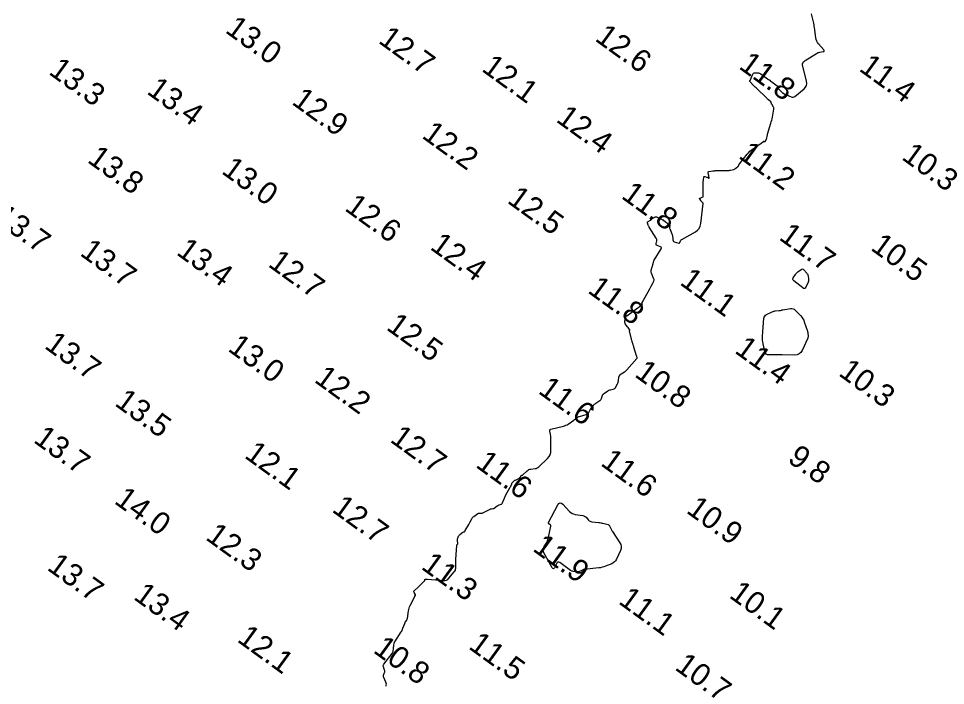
# Model space of a CAD drawing. Extents: x 815352 to 820877, y 582403 to 597439.
# Drawn here: x 818763.1 to 818971.4, y 587063.7 to 587213.7 of the extents above; entities that cross this region are included whole.
import ezdxf

# ---------------------------------------------------------------- set-up
doc = ezdxf.new("R2010")
doc.units = 0
doc.layers.add('V-CONT-EL12', color=7, linetype='Continuous')
doc.layers.add('V-TOPO-SOUN', color=7, linetype='Continuous')

msp = doc.modelspace()

# ---------------------------------------------------------------- linework, layer by layer
at = {"layer": 'V-CONT-EL12'}
msp.add_lwpolyline([(818845.72, 587063.57), (818845.78, 587063.79), (818845.8, 587064), (818845.77, 587064.21), (818845.7, 587064.41), (818845.21, 587065.49), (818845.17, 587065.62), (818845.15, 587065.76), (818845.16, 587065.9), (818845.19, 587066.03), (818845.38, 587066.59), (818845.42, 587066.73), (818845.43, 587066.87), (818845.42, 587067.01), (818845.38, 587067.15), (818845.14, 587067.86), (818845.1, 587068.02), (818845.11, 587068.17), (818845.15, 587068.32), (818845.24, 587068.46), (818847.11, 587070.91), (818847.18, 587071.02), (818847.24, 587071.13), (818847.28, 587071.25), (818847.3, 587071.38), (818847.4, 587072.05), (818847.4, 587072.11), (818847.41, 587072.17), (818847.42, 587072.23), (818847.43, 587072.28), (818847.45, 587072.51), (818847.46, 587072.57), (818847.47, 587072.63), (818847.48, 587072.69), (818847.49, 587072.74), (818847.57, 587073.2), (818847.59, 587073.29), (818847.62, 587073.38), (818847.66, 587073.46), (818847.7, 587073.55), (818849.13, 587075.76), (818849.24, 587075.95), (818849.35, 587076.15), (818849.44, 587076.35), (818849.53, 587076.56), (818849.92, 587077.62), (818849.96, 587077.72), (818850.01, 587077.82), (818850.06, 587077.92), (818850.12, 587078.01), (818850.37, 587078.38), (818850.43, 587078.48), (818850.47, 587078.58), (818850.51, 587078.68), (818850.53, 587078.79), (818850.78, 587080.47), (818850.84, 587080.79), (818850.92, 587081.09), (818851.03, 587081.39), (818851.16, 587081.68), (818852.1, 587083.56), (818852.12, 587083.62), (818852.15, 587083.67), (818852.18, 587083.73), (818852.2, 587083.79), (818852.31, 587084.01), (818852.32, 587084.07), (818852.33, 587084.12), (818852.32, 587084.18), (818852.29, 587084.23), (818852.01, 587084.64), (818851.97, 587084.72), (818851.96, 587084.8), (818851.99, 587084.88), (818852.05, 587084.95), (818852.92, 587085.8), (818853.06, 587085.94), (818853.21, 587086.08), (818853.36, 587086.22), (818853.5, 587086.36), (818854.32, 587087.14), (818854.35, 587087.18), (818854.38, 587087.22), (818854.4, 587087.26), (818854.42, 587087.31), (818854.48, 587087.5), (818854.5, 587087.54), (818854.53, 587087.57), (818854.57, 587087.59), (818854.61, 587087.6), (818854.82, 587087.61), (818854.87, 587087.62), (818854.92, 587087.62), (818854.97, 587087.62), (818855.02, 587087.61), (818858.57, 587087.27), (818858.94, 587087.28), (818859.28, 587087.37), (818859.59, 587087.54), (818859.86, 587087.8), (818861.07, 587089.22), (818861.21, 587089.41), (818861.31, 587089.62), (818861.37, 587089.84), (818861.39, 587090.07), (818861.39, 587091.03), (818861.39, 587091.27), (818861.39, 587091.51), (818861.4, 587091.75), (818861.42, 587091.99), (818861.64, 587095.23), (818861.64, 587095.28), (818861.66, 587095.31), (818861.68, 587095.35), (818861.7, 587095.38), (818861.82, 587095.51), (818861.85, 587095.54), (818861.86, 587095.58), (818861.87, 587095.62), (818861.87, 587095.66), (818861.79, 587096.32), (818861.78, 587096.44), (818861.79, 587096.56), (818861.82, 587096.67), (818861.85, 587096.79), (818862.04, 587097.24), (818862.1, 587097.35), (818862.16, 587097.45), (818862.24, 587097.54), (818862.33, 587097.62), (818862.99, 587098.14), (818863.02, 587098.17), (818863.06, 587098.19), (818863.1, 587098.21), (818863.14, 587098.22), (818863.34, 587098.28), (818863.37, 587098.29), (818863.39, 587098.3), (818863.41, 587098.32), (818863.43, 587098.34), (818863.48, 587098.45), (818863.5, 587098.47), (818863.51, 587098.5), (818863.53, 587098.53), (818863.54, 587098.55), (818864.31, 587099.87), (818864.4, 587100.02), (818864.49, 587100.19), (818864.58, 587100.35), (818864.66, 587100.51), (818864.99, 587101.18), (818865.08, 587101.33), (818865.19, 587101.48), (818865.31, 587101.61), (818865.45, 587101.72), (818866.33, 587102.35), (818866.41, 587102.4), (818866.51, 587102.43), (818866.6, 587102.45), (818866.71, 587102.46), (818867.12, 587102.43), (818867.22, 587102.43), (818867.32, 587102.45), (818867.42, 587102.48), (818867.51, 587102.52), (818869.11, 587103.36), (818869.18, 587103.39), (818869.26, 587103.42), (818869.34, 587103.44), (818869.42, 587103.45), (818869.75, 587103.46), (818869.83, 587103.47), (818869.9, 587103.49), (818869.97, 587103.52), (818870.04, 587103.57), (818870.72, 587104.07), (818870.82, 587104.14), (818870.92, 587104.2), (818871.02, 587104.25), (818871.13, 587104.29), (818871.57, 587104.45), (818871.67, 587104.5), (818871.76, 587104.56), (818871.82, 587104.65), (818871.88, 587104.75), (818872.25, 587105.66), (818872.33, 587105.85), (818872.41, 587106.04), (818872.51, 587106.22), (818872.6, 587106.4), (818873.65, 587108.27), (818873.7, 587108.37), (818873.75, 587108.46), (818873.79, 587108.56), (818873.83, 587108.66), (818873.99, 587109.07), (818874.03, 587109.16), (818874.07, 587109.24), (818874.13, 587109.32), (818874.19, 587109.39), (818874.47, 587109.67), (818874.54, 587109.73), (818874.61, 587109.79), (818874.7, 587109.84), (818874.78, 587109.89), (818875.58, 587110.27), (818875.66, 587110.31), (818875.73, 587110.37), (818875.8, 587110.43), (818875.85, 587110.5), (818876.12, 587110.91), (818876.14, 587110.94), (818876.17, 587110.96), (818876.2, 587110.98), (818876.23, 587110.99), (818876.37, 587111.02), (818876.4, 587111.03), (818876.44, 587111.04), (818876.47, 587111.06), (818876.49, 587111.08), (818877.46, 587111.98), (818877.64, 587112.12), (818877.83, 587112.23), (818878.04, 587112.31), (818878.27, 587112.35), (818879.22, 587112.47), (818879.45, 587112.52), (818879.66, 587112.6), (818879.85, 587112.71), (818880.03, 587112.86), (818882.02, 587114.76), (818882.36, 587115.16), (818882.6, 587115.59), (818882.74, 587116.07), (818882.78, 587116.59), (818882.72, 587119.85), (818882.71, 587120), (818882.69, 587120.14), (818882.67, 587120.28), (818882.64, 587120.42), (818882.51, 587120.97), (818882.5, 587121.1), (818882.53, 587121.2), (818882.6, 587121.27), (818882.72, 587121.32), (818885.58, 587122.01), (818885.86, 587122.09), (818886.13, 587122.2), (818886.39, 587122.33), (818886.64, 587122.49), (818887.89, 587123.36), (818887.99, 587123.43), (818888.1, 587123.51), (818888.2, 587123.59), (818888.3, 587123.67), (818888.71, 587123.99), (818888.82, 587124.06), (818888.93, 587124.12), (818889.04, 587124.17), (818889.17, 587124.21), (818890.71, 587124.61), (818890.9, 587124.68), (818891.06, 587124.78), (818891.2, 587124.92), (818891.3, 587125.09), (818891.75, 587126.01), (818891.8, 587126.11), (818891.86, 587126.21), (818891.93, 587126.31), (818892, 587126.4), (818892.31, 587126.75), (818892.39, 587126.83), (818892.48, 587126.91), (818892.57, 587126.99), (818892.66, 587127.05), (818893.8, 587127.78), (818893.91, 587127.86), (818894, 587127.97), (818894.07, 587128.08), (818894.12, 587128.22), (818894.28, 587128.78), (818894.33, 587128.92), (818894.4, 587129.04), (818894.49, 587129.15), (818894.6, 587129.24), (818895.54, 587129.95), (818895.68, 587130.04), (818895.82, 587130.11), (818895.98, 587130.17), (818896.14, 587130.21), (818896.8, 587130.34), (818896.96, 587130.38), (818897.09, 587130.46), (818897.2, 587130.57), (818897.29, 587130.7), (818897.74, 587131.54), (818897.82, 587131.7), (818897.88, 587131.86), (818897.92, 587132.02), (818897.95, 587132.19), (818898.07, 587133.08), (818898.08, 587133.15), (818898.1, 587133.21), (818898.13, 587133.27), (818898.17, 587133.33), (818898.33, 587133.55), (818898.38, 587133.6), (818898.43, 587133.65), (818898.48, 587133.7), (818898.53, 587133.74), (818899.3, 587134.23), (818899.45, 587134.33), (818899.58, 587134.43), (818899.71, 587134.55), (818899.83, 587134.68), (818902.11, 587137.24), (818902.14, 587137.28), (818902.16, 587137.33), (818902.16, 587137.37), (818902.16, 587137.42), (818902.1, 587137.62), (818902.09, 587137.67), (818902.07, 587137.72), (818902.06, 587137.77), (818902.04, 587137.82), (818901.42, 587139.75), (818901.37, 587139.9), (818901.33, 587140.05), (818901.28, 587140.2), (818901.23, 587140.35), (818901.04, 587140.94), (818901, 587141.09), (818900.96, 587141.24), (818900.92, 587141.39), (818900.88, 587141.54), (818900.46, 587143.44), (818900.46, 587143.46), (818900.46, 587143.48), (818900.47, 587143.51), (818900.47, 587143.53), (818900.51, 587143.61), (818900.52, 587143.63), (818900.52, 587143.65), (818900.51, 587143.67), (818900.5, 587143.68), (818900.23, 587144.03), (818900.19, 587144.1), (818900.14, 587144.16), (818900.08, 587144.23), (818900.03, 587144.29), (818899.59, 587144.81), (818899.54, 587144.88), (818899.51, 587144.96), (818899.48, 587145.04), (818899.46, 587145.12), (818899.42, 587145.47), (818899.42, 587145.55), (818899.42, 587145.64), (818899.42, 587145.73), (818899.44, 587145.81), (818899.55, 587146.42), (818899.59, 587146.54), (818899.64, 587146.65), (818899.72, 587146.75), (818899.81, 587146.83), (818902.63, 587148.86), (818902.7, 587148.9), (818902.77, 587148.95), (818902.84, 587149), (818902.91, 587149.05), (818903.25, 587149.28), (818903.29, 587149.31), (818903.31, 587149.34), (818903.32, 587149.39), (818903.31, 587149.43), (818903.25, 587149.63), (818903.24, 587149.68), (818903.24, 587149.73), (818903.25, 587149.77), (818903.27, 587149.82), (818904.98, 587152.87), (818905.07, 587153.03), (818905.15, 587153.18), (818905.24, 587153.34), (818905.32, 587153.5), (818905.77, 587154.33), (818905.8, 587154.39), (818905.82, 587154.44), (818905.85, 587154.5), (818905.86, 587154.56), (818905.94, 587154.81), (818905.95, 587154.87), (818905.95, 587154.93), (818905.94, 587154.99), (818905.92, 587155.05), (818905.35, 587156.39), (818905.3, 587156.55), (818905.28, 587156.72), (818905.28, 587156.89), (818905.32, 587157.06), (818905.55, 587157.83), (818905.59, 587157.96), (818905.63, 587158.08), (818905.66, 587158.21), (818905.69, 587158.34), (818905.8, 587158.86), (818905.83, 587158.98), (818905.87, 587159.11), (818905.92, 587159.23), (818905.99, 587159.34), (818907.54, 587161.85), (818907.61, 587161.99), (818907.6, 587162.12), (818907.53, 587162.23), (818907.39, 587162.31), (818906.64, 587162.61), (818906.51, 587162.68), (818906.43, 587162.78), (818906.4, 587162.9), (818906.41, 587163.05), (818906.55, 587163.68), (818906.57, 587163.84), (818906.56, 587163.99), (818906.52, 587164.13), (818906.44, 587164.27), (818904.89, 587166.73), (818904.82, 587166.84), (818904.76, 587166.96), (818904.71, 587167.08), (818904.66, 587167.2), (818904.48, 587167.73), (818904.46, 587167.83), (818904.47, 587167.91), (818904.52, 587167.98), (818904.6, 587168.03), (818905.15, 587168.29), (818905.17, 587168.3), (818905.19, 587168.31), (818905.2, 587168.33), (818905.22, 587168.36), (818905.25, 587168.46), (818905.26, 587168.48), (818905.28, 587168.5), (818905.29, 587168.52), (818905.32, 587168.53), (818906.09, 587168.98), (818906.22, 587169.04), (818906.36, 587169.06), (818906.5, 587169.05), (818906.65, 587169.01), (818907.64, 587168.55), (818907.76, 587168.5), (818907.87, 587168.43), (818907.99, 587168.36), (818908.09, 587168.29), (818908.53, 587167.96), (818908.62, 587167.88), (818908.72, 587167.81), (818908.82, 587167.73), (818908.92, 587167.66), (818909.39, 587167.3), (818909.44, 587167.25), (818909.47, 587167.19), (818909.49, 587167.13), (818909.49, 587167.06), (818909.45, 587166.76), (818909.44, 587166.69), (818909.44, 587166.62), (818909.45, 587166.54), (818909.48, 587166.47), (818910.02, 587165), (818910.06, 587164.86), (818910.1, 587164.72), (818910.13, 587164.58), (818910.14, 587164.43), (818910.19, 587163.85), (818910.22, 587163.72), (818910.28, 587163.61), (818910.37, 587163.53), (818910.49, 587163.48), (818911.5, 587163.18), (818911.59, 587163.17), (818911.67, 587163.19), (818911.73, 587163.24), (818911.77, 587163.32), (818911.93, 587163.7), (818911.97, 587163.8), (818912.03, 587163.88), (818912.1, 587163.94), (818912.19, 587164), (818915.23, 587165.72), (818915.7, 587166.06), (818916.07, 587166.48), (818916.31, 587166.98), (818916.44, 587167.56), (818916.95, 587172.05), (818916.95, 587172.12), (818916.94, 587172.19), (818916.9, 587172.25), (818916.85, 587172.3), (818916.62, 587172.51), (818916.57, 587172.56), (818916.52, 587172.61), (818916.47, 587172.67), (818916.43, 587172.74), (818916.22, 587173.08), (818916.19, 587173.15), (818916.19, 587173.22), (818916.22, 587173.27), (818916.3, 587173.3), (818916.79, 587173.48), (818916.89, 587173.53), (818916.96, 587173.6), (818917, 587173.69), (818917.01, 587173.8), (818917.01, 587176.78), (818917.02, 587176.93), (818917.02, 587177.07), (818917.03, 587177.21), (818917.05, 587177.35), (818917.12, 587178.01), (818917.14, 587178.09), (818917.19, 587178.14), (818917.25, 587178.16), (818917.33, 587178.14), (818917.77, 587178), (818917.83, 587177.98), (818917.9, 587177.95), (818917.95, 587177.93), (818918.01, 587177.9), (818918.25, 587177.79), (818918.3, 587177.77), (818918.33, 587177.78), (818918.34, 587177.81), (818918.34, 587177.86), (818918.29, 587178.21), (818918.27, 587178.29), (818918.26, 587178.37), (818918.24, 587178.45), (818918.21, 587178.53), (818918.08, 587179), (818918.06, 587179.09), (818918.08, 587179.16), (818918.14, 587179.21), (818918.23, 587179.24), (818919.14, 587179.39), (818919.33, 587179.42), (818919.52, 587179.44), (818919.71, 587179.45), (818919.9, 587179.46), (818922.49, 587179.49), (818922.66, 587179.5), (818922.83, 587179.51), (818922.99, 587179.54), (818923.16, 587179.57), (818923.87, 587179.73), (818924.01, 587179.77), (818924.13, 587179.83), (818924.24, 587179.9), (818924.34, 587179.99), (818924.86, 587180.49), (818924.9, 587180.53), (818924.93, 587180.57), (818924.97, 587180.62), (818924.99, 587180.67), (818925.09, 587180.89), (818925.12, 587180.94), (818925.15, 587180.99), (818925.18, 587181.04), (818925.21, 587181.08), (818926.88, 587183.14), (818927.18, 587183.48), (818927.5, 587183.8), (818927.85, 587184.11), (818928.21, 587184.38), (818930.52, 587186.03), (818930.55, 587186.05), (818930.58, 587186.05), (818930.62, 587186.05), (818930.65, 587186.04), (818930.78, 587185.97), (818930.81, 587185.96), (818930.84, 587185.96), (818930.86, 587185.97), (818930.89, 587186), (818931.13, 587186.39), (818931.17, 587186.47), (818931.21, 587186.55), (818931.24, 587186.63), (818931.26, 587186.72), (818931.37, 587187.2), (818931.4, 587187.31), (818931.42, 587187.42), (818931.45, 587187.53), (818931.48, 587187.64), (818932.2, 587190.12), (818932.29, 587190.45), (818932.38, 587190.79), (818932.46, 587191.13), (818932.53, 587191.47), (818932.88, 587193.24), (818932.9, 587193.37), (818932.89, 587193.5), (818932.85, 587193.63), (818932.79, 587193.75), (818932.38, 587194.39), (818932.36, 587194.43), (818932.34, 587194.47), (818932.33, 587194.52), (818932.31, 587194.56), (818932.28, 587194.75), (818932.26, 587194.79), (818932.24, 587194.84), (818932.22, 587194.87), (818932.19, 587194.91), (818931.67, 587195.38), (818931.58, 587195.47), (818931.48, 587195.56), (818931.38, 587195.65), (818931.29, 587195.75), (818929.02, 587197.91), (818928.86, 587198.07), (818928.7, 587198.22), (818928.54, 587198.38), (818928.38, 587198.54), (818927.47, 587199.46), (818927.45, 587199.48), (818927.45, 587199.5), (818927.44, 587199.52), (818927.45, 587199.54), (818927.49, 587199.65), (818927.5, 587199.67), (818927.51, 587199.7), (818927.52, 587199.72), (818927.53, 587199.75), (818928.14, 587201.13), (818928.22, 587201.26), (818928.33, 587201.36), (818928.46, 587201.41), (818928.62, 587201.43), (818929.31, 587201.41), (818929.47, 587201.39), (818929.63, 587201.35), (818929.78, 587201.29), (818929.93, 587201.2), (818931.48, 587200.08), (818931.7, 587199.92), (818931.93, 587199.76), (818932.15, 587199.6), (818932.38, 587199.44), (818933.65, 587198.54), (818933.69, 587198.51), (818933.71, 587198.47), (818933.73, 587198.42), (818933.72, 587198.37), (818933.69, 587198.16), (818933.69, 587198.11), (818933.7, 587198.06), (818933.72, 587198.02), (818933.75, 587197.98), (818934.7, 587197.11), (818934.77, 587197.04), (818934.85, 587196.98), (818934.92, 587196.92), (818935, 587196.87), (818935.33, 587196.65), (818935.41, 587196.6), (818935.5, 587196.55), (818935.59, 587196.51), (818935.68, 587196.47), (818936.79, 587196.04), (818937, 587195.98), (818937.21, 587195.98), (818937.4, 587196.04), (818937.58, 587196.16), (818939.67, 587197.86), (818940.01, 587198.21), (818940.21, 587198.61), (818940.29, 587199.05), (818940.23, 587199.54), (818939.32, 587203.24), (818939.3, 587203.34), (818939.31, 587203.43), (818939.34, 587203.52), (818939.39, 587203.6), (818939.64, 587203.93), (818939.7, 587204.01), (818939.77, 587204.08), (818939.85, 587204.14), (818939.93, 587204.2), (818942.48, 587205.82), (818942.65, 587205.92), (818942.82, 587205.99), (818943.01, 587206.05), (818943.2, 587206.09), (818943.96, 587206.23), (818944.12, 587206.27), (818944.19, 587206.35), (818944.18, 587206.45), (818944.09, 587206.59), (818942.89, 587207.98), (818942.67, 587208.27), (818942.5, 587208.59), (818942.38, 587208.92), (818942.31, 587209.28), (818942, 587211.61), (818941.96, 587211.94), (818941.9, 587212.26), (818941.84, 587212.58), (818941.76, 587212.89), (818941.31, 587214.69)], dxfattribs=at)
for points in [[(818937.2, 587154.81), (818937.13, 587154.97), (818937.14, 587155.14), (818937.22, 587155.33), (818937.7, 587156.1), (818937.83, 587156.27), (818937.96, 587156.44), (818938.12, 587156.59), (818938.29, 587156.72), (818939, 587157.23), (818939.17, 587157.32), (818939.34, 587157.34), (818939.49, 587157.28), (818939.64, 587157.15), (818940.29, 587156.39), (818940.39, 587156.25), (818940.47, 587156.1), (818940.53, 587155.94), (818940.56, 587155.77), (818940.66, 587155.07), (818940.67, 587154.9), (818940.66, 587154.73), (818940.62, 587154.57), (818940.56, 587154.41), (818940.02, 587153.24), (818939.89, 587153.05), (818939.74, 587152.96), (818939.56, 587152.97), (818939.36, 587153.09), (818937.34, 587154.67)], [(818934.4, 587138.02), (818934.02, 587138.02), (818933.64, 587138.02), (818933.26, 587138.02), (818931.75, 587138.02), (818931.41, 587138.07), (818931.15, 587138.2), (818930.96, 587138.44), (818930.84, 587138.76), (818930.46, 587140.52), (818930.39, 587140.94), (818930.34, 587141.36), (818930.33, 587141.79), (818930.35, 587142.21), (818930.65, 587146.25), (818930.71, 587146.52), (818930.82, 587146.76), (818931, 587146.95), (818931.23, 587147.1), (818932.52, 587147.74), (818932.68, 587147.81), (818932.84, 587147.86), (818933.01, 587147.89), (818933.18, 587147.91), (818934.07, 587147.98), (818934.14, 587147.99), (818934.21, 587148), (818934.28, 587148.01), (818934.35, 587148.03), (818934.62, 587148.11), (818934.69, 587148.13), (818934.76, 587148.15), (818934.82, 587148.16), (818934.89, 587148.18), (818936.61, 587148.45), (818936.91, 587148.47), (818937.18, 587148.41), (818937.44, 587148.29), (818937.66, 587148.1), (818938.9, 587146.8), (818939.16, 587146.5), (818939.38, 587146.17), (818939.57, 587145.83), (818939.71, 587145.46), (818940.41, 587143.37), (818940.45, 587143.24), (818940.48, 587143.11), (818940.5, 587142.98), (818940.52, 587142.85), (818940.57, 587142.33), (818940.57, 587142.2), (818940.56, 587142.07), (818940.53, 587141.95), (818940.49, 587141.82), (818939.2, 587139), (818938.93, 587138.56), (818938.58, 587138.24), (818938.14, 587138.05), (818937.62, 587137.99), (818934.77, 587138.01)], [(818890.15, 587089.78), (818890.1, 587089.76), (818890.04, 587089.74), (818889.99, 587089.71), (818889.8, 587089.58), (818889.76, 587089.55), (818889.71, 587089.52), (818889.65, 587089.49), (818889.6, 587089.48), (818888.91, 587089.26), (818888.78, 587089.23), (818888.64, 587089.21), (818888.51, 587089.21), (818888.37, 587089.23), (818887.74, 587089.34), (818887.6, 587089.38), (818887.46, 587089.43), (818887.32, 587089.49), (818887.2, 587089.57), (818884.76, 587091.34), (818884.55, 587091.45), (818884.36, 587091.46), (818884.2, 587091.36), (818884.07, 587091.17), (818883.57, 587090.18), (818883.45, 587090), (818883.33, 587089.93), (818883.2, 587089.99), (818883.07, 587090.17), (818881.13, 587093.7), (818881.09, 587093.8), (818881.06, 587093.9), (818881.05, 587094), (818881.06, 587094.1), (818881.13, 587094.53), (818881.15, 587094.63), (818881.18, 587094.73), (818881.22, 587094.83), (818881.27, 587094.92), (818881.85, 587095.86), (818881.96, 587096.05), (818882.04, 587096.25), (818882.12, 587096.45), (818882.17, 587096.66), (818882.76, 587099.54), (818882.77, 587099.63), (818882.75, 587099.71), (818882.71, 587099.78), (818882.64, 587099.84), (818882.34, 587100.07), (818882.27, 587100.14), (818882.24, 587100.2), (818882.24, 587100.28), (818882.27, 587100.36), (818884.35, 587104.31), (818884.59, 587104.65), (818884.86, 587104.78), (818885.15, 587104.72), (818885.47, 587104.46), (818886.96, 587102.83), (818887.22, 587102.59), (818887.52, 587102.4), (818887.84, 587102.26), (818888.19, 587102.17), (818889.95, 587101.9), (818890.16, 587101.85), (818890.35, 587101.77), (818890.52, 587101.65), (818890.67, 587101.51), (818891.25, 587100.87), (818891.4, 587100.73), (818891.57, 587100.62), (818891.76, 587100.55), (818891.96, 587100.51), (818893.47, 587100.36), (818893.72, 587100.33), (818893.97, 587100.28), (818894.22, 587100.23), (818894.46, 587100.17), (818895.61, 587099.87), (818895.75, 587099.81), (818895.88, 587099.73), (818895.97, 587099.61), (818896.05, 587099.48), (818896.3, 587098.87), (818896.36, 587098.72), (818896.43, 587098.57), (818896.51, 587098.43), (818896.6, 587098.29), (818898.26, 587095.79), (818898.48, 587095.38), (818898.57, 587094.95), (818898.55, 587094.51), (818898.4, 587094.07), (818897.51, 587092.08), (818897.32, 587091.75), (818897.09, 587091.47), (818896.8, 587091.25), (818896.46, 587091.08), (818895.01, 587090.51), (818894.65, 587090.38), (818894.28, 587090.27), (818893.9, 587090.19), (818893.51, 587090.14), (818890.21, 587089.79)]]:
    msp.add_lwpolyline(points, close=True, dxfattribs=at)

# ---------------------------------------------------------------- texts
at = {"layer": 'V-TOPO-SOUN'}
for s, p in [('13.0 ', (818809.36, 587210.68)), ('12.7 ', (818843.78, 587208.34)), ('12.6 ', (818892.44, 587208.83)), ('13.3 ', (818769.7, 587201.32)), ('12.1 ', (818866.99, 587202)), ('11.8 ', (818924.78, 587202.57)), ('11.4 ', (818951.78, 587202.07)), ('13.4 ', (818791.74, 587196.92)), ('12.9 ', (818824.32, 587194.56)), ('12.4 ', (818883.7, 587190.62)), ('12.2 ', (818853.55, 587186.98)), ('11.2 ', (818924.72, 587182.45)), ('13.8 ', (818778.39, 587181.5)), ('10.3 ', (818961.36, 587182.16)), ('13.0 ', (818808.54, 587178.99)), ('12.5 ', (818872.74, 587172.38)), ('11.8 ', (818898.37, 587173.4)), ('12.6 ', (818836.21, 587170.67)), ('13.7 ', (818757.43, 587168.28)), ('11.7 ', (818933.8, 587164.11)), ('12.4 ', (818855.39, 587161.95)), ('10.5 ', (818954.4, 587161.78)), ('13.7 ', (818776.72, 587160.57)), ('13.4 ', (818798.4, 587160.74)), ('12.7 ', (818819.01, 587158.08)), ('11.1 ', (818911.51, 587154)), ('11.8 ', (818890.82, 587152.17)), ('12.5 ', (818845.57, 587143.87)), ('13.7 ', (818768.74, 587139.7)), ('13.0 ', (818809.96, 587139.09)), ('11.4 ', (818923.83, 587138.66)), ('10.8 ', (818901.36, 587133.31)), ('10.3 ', (818947.19, 587133.57)), ('12.2 ', (818829.37, 587132.09)), ('11.6 ', (818879.71, 587129.56)), ('13.5 ', (818784.52, 587126.81)), ('13.7 ', (818766.28, 587118.54)), ('12.7 ', (818846.4, 587118.64)), ('12.1 ', (818813.68, 587115.06)), ('9.8', (818935.72, 587114.16)), ('11.6 ', (818865.64, 587112.96)), ('11.6 ', (818893.72, 587113.35)), ('14.0 ', (818784.43, 587104.81)), ('12.7 ', (818833.34, 587102.93)), ('10.9 ', (818912.97, 587102.7)), ('12.3 ', (818804.96, 587096.66)), ('11.9 ', (818878.46, 587094.13)), ('13.7 ', (818769.33, 587089.87)), ('11.3 ', (818853.39, 587090.07)), ('13.4 ', (818788.76, 587083.27)), ('11.1 ', (818897.73, 587082.28)), ('10.1 ', (818922.6, 587083.63)), ('12.1 ', (818812.04, 587073.72)), ('11.5 ', (818864.04, 587072.15)), ('10.8 ', (818842.63, 587071.27)), ('10.7 ', (818910.38, 587067.43))]:
    msp.add_text(s, height=5, rotation=324, dxfattribs=at).set_placement(p)

doc.saveas('drawing.dxf')
